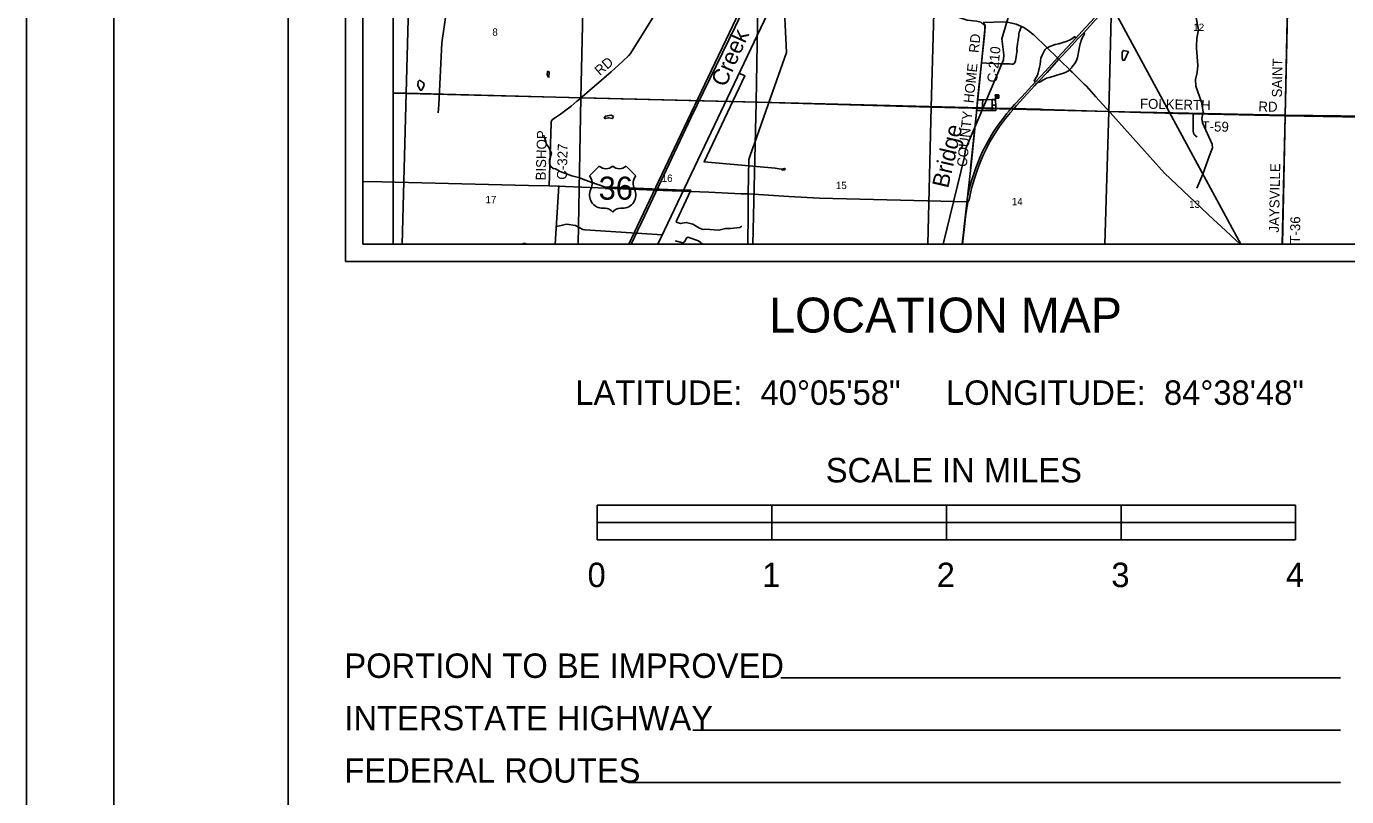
# Model space of a CAD drawing. Extents: x 0 to 68.9, y -26.1 to 22.
# Drawn here: x 0 to 7.56, y 10.94 to 15.35 of the extents above; entities that cross this region are included whole.
import ezdxf

# ---------------------------------------------------------------- set-up
doc = ezdxf.new("R2010")
doc.units = 0
for name, color, linetype in [('GM_X_Corporation', 7, 'Continuous'), ('GM_X_County_Road', 7, 'Continuous'), ('GM_X_County_Road_Text', 7, 'Continuous'), ('GM_X_Interchange_Ramps', 7, 'Continuous'), ('GM_X_Minor_Lake', 7, 'Continuous'), ('GM_X_Minor_River', 7, 'Continuous'), ('GM_X_Minor_River_Text', 7, 'Continuous'), ('GM_X_Rail_Line', 7, 'Continuous'), ('GM_X_Section_Text', 7, 'Continuous'), ('GM_X_State_Route', 7, 'Continuous'), ('GM_X_Township_Road', 7, 'Continuous'), ('GM_X_Township_Road_Text', 7, 'Continuous'), ('GM_X_US_Location', 7, 'Continuous'), ('GM_X_US_Route', 7, 'Continuous'), ('GM_X_US_Shield', 7, 'Continuous'), ('SH_Border', 7, 'Continuous'), ('SH_Cut_Line', 7, 'Continuous'), ('SH_Data', 7, 'Continuous'), ('SH_Text', 7, 'Continuous')]:
    doc.layers.add(name, color=color, linetype=linetype)

msp = doc.modelspace()

# ---------------------------------------------------------------- linework, layer by layer
at = {"layer": 'GM_X_Corporation'}
for points in [[(7.3445, 20.9), (2.1, 20.9), (2.1, 14.9646), (3.342, 14.9339), (4.4236, 14.9071), (5.6162, 14.8776), (5.6466, 14.8768), (5.7051, 14.8754), (5.7249, 14.8749), (5.8078, 14.8728), (5.8237, 14.8724), (6.3807, 14.8544), (6.5963, 14.8495), (6.6831, 14.8475), (7.2088, 14.8355), (7.7563, 14.8264), (8.2579, 14.8244), (8.6486, 14.8265), (8.7556, 14.8254), (8.9, 14.8227), (8.9, 20.8594), (8.5115, 20.8629), (7.8412, 20.8763), (7.3443, 20.8819)], [(2.1, 15.9546), (2.1, 14.9678), (2.1744, 14.9657), (2.2018, 15.9573)], [(2.2018, 15.9573), (3.1993, 15.9361), (3.1762, 14.938), (2.1744, 14.9657)], [(3.1993, 15.9361), (4.1977, 15.9225), (4.1789, 14.914), (3.1762, 14.938)], [(4.1977, 15.9225), (5.2101, 15.8972), (5.1829, 14.8851), (4.1789, 14.914)], [(5.2101, 15.8972), (6.224, 15.8733), (6.2001, 14.86), (5.1829, 14.8851)], [(6.224, 15.8733), (7.2305, 15.8522), (7.2304, 15.8453), (7.2092, 14.8389), (6.2001, 14.86)], [(8.019, 15.8387), (8.0065, 14.829), (7.2092, 14.8389), (7.2304, 15.8453)], [(2.1, 14.9678), (2.1, 14.1), (2.1524, 14.1), (2.1744, 14.9657)], [(2.1, 14.9646), (2.1, 14.1), (7.1934, 14.1), (7.2088, 14.8355), (6.6831, 14.8475), (6.5963, 14.8495), (6.3807, 14.8544), (5.8237, 14.8724), (5.8078, 14.8728), (5.7249, 14.8749), (5.7051, 14.8754), (5.6466, 14.8768), (5.6162, 14.8776), (4.4236, 14.9071), (3.342, 14.9339)], [(2.1524, 14.1), (3.1596, 14.1), (3.1762, 14.938), (2.1744, 14.9657)], [(3.1596, 14.1), (4.16, 14.1), (4.1789, 14.914), (3.1762, 14.938)], [(4.16, 14.1), (5.1627, 14.1), (5.1829, 14.8851), (4.1789, 14.914)], [(5.1627, 14.1), (6.1766, 14.1), (6.2001, 14.86), (5.1829, 14.8851)], [(6.1766, 14.1), (7.1943, 14.1), (7.2092, 14.8389), (6.2001, 14.86)], [(7.1934, 14.1), (8.9, 14.1), (8.9, 14.8227), (8.7556, 14.8254), (8.6486, 14.8265), (8.2579, 14.8244), (7.7563, 14.8264), (7.2088, 14.8355)], [(7.1943, 14.1), (8.0027, 14.1), (8.0065, 14.829), (7.2092, 14.8389)]]:
    msp.add_lwpolyline(points, close=True, dxfattribs=at)
at = {"layer": 'GM_X_County_Road'}
for p, q in [((5.532, 14.8967), (5.5316, 14.928)), ((5.532, 14.8967), (5.552, 14.8973)), ((5.5419, 14.928), (5.5512, 14.9199)), ((5.5498, 14.9454), (5.5693, 14.9454)), ((5.4071, 14.5356), (5.4413, 14.8553)), ((5.4423, 14.865), (5.4731, 14.8655))]:
    msp.add_line(p, q, dxfattribs=at)
for points in [[(3.1578, 14.9235), (3.1692, 14.9333), (3.3487, 15.0882), (3.417, 15.1494), (3.4479, 15.1782), (3.4593, 15.1916), (3.5611, 15.3554), (3.5951, 15.4107), (3.6052, 15.4306), (3.6308, 15.5213), (3.7157, 15.8576), (3.7173, 15.8579), (3.8308, 15.8195), (3.8677, 15.807), (3.9004, 15.7954), (3.9289, 15.7828), (3.9544, 15.7713), (4.0004, 15.7479), (4.0281, 15.7353), (4.0515, 15.7285), (4.2089, 15.7174)], [(5.4413, 14.8553), (5.4423, 14.865), (5.4435, 14.877), (5.4484, 14.9277), (5.4712, 15.1394), (5.4871, 15.297), (5.4923, 15.3449), (5.4911, 15.3529), (5.4798, 15.3701)], [(5.4712, 15.1394), (5.499, 15.1369), (5.5375, 15.1351), (5.5782, 15.1336), (5.6076, 15.1332), (5.6314, 15.1326), (5.6435, 15.1315), (5.6505, 15.1318), (5.6544, 15.1332), (5.6579, 15.1351), (5.6602, 15.1376), (5.6614, 15.1403), (5.6627, 15.1439), (5.6643, 15.1498), (5.6683, 15.1748), (5.6708, 15.187), (5.6734, 15.1998), (5.6738, 15.2087), (5.6735, 15.2153), (5.6733, 15.2218), (5.674, 15.2302), (5.6762, 15.2469), (5.6804, 15.2711), (5.6835, 15.2946), (5.685, 15.3051), (5.6865, 15.3153), (5.689, 15.323), (5.6935, 15.3329), (5.6996, 15.3464)], [(2.9943, 14.434), (3.0051, 14.7942), (3.0061, 14.8022), (3.0113, 14.8115), (3.0242, 14.8218), (3.0587, 14.8452), (3.0979, 14.8733), (3.1197, 14.8906), (3.1533, 14.9195), (3.1578, 14.9235)], [(5.4484, 14.9277), (5.4774, 14.9272), (5.5316, 14.928), (5.539, 14.928)], [(5.4731, 14.8655), (5.5324, 14.8657), (5.5523, 14.8655), (5.5522, 14.8744), (5.552, 14.8973), (5.5512, 14.9199), (5.5509, 14.928)], [(5.4731, 14.8655), (5.4738, 14.8763), (5.4774, 14.9272)], [(5.5324, 14.8657), (5.5323, 14.8748), (5.532, 14.8967)], [(5.539, 14.928), (5.5419, 14.928), (5.5509, 14.928), (5.5504, 14.9361), (5.5498, 14.9454), (5.5492, 14.9548), (5.5689, 14.9548), (5.5693, 14.9454), (5.5696, 14.9364), (5.5504, 14.9361)]]:
    msp.add_lwpolyline(points, dxfattribs=at)
at = {"layer": 'GM_X_Interchange_Ramps'}
for points in [[(6.012, 15.282), (6.0053, 15.2887), (6.0034, 15.2872), (5.9877, 15.2769), (5.9739, 15.2691), (5.9553, 15.2611), (5.9356, 15.2547), (5.9126, 15.2486), (5.8924, 15.2434), (5.8779, 15.2381), (5.8612, 15.2319), (5.8542, 15.2282), (5.8501, 15.2265), (5.8459, 15.2253)], [(5.9751, 15.0992), (5.9771, 15.1013), (5.985, 15.1109), (5.9877, 15.1139), (5.9962, 15.1239), (6.0045, 15.1346), (6.011, 15.1454), (6.0167, 15.1581), (6.0202, 15.1692), (6.0228, 15.1788), (6.032, 15.2308), (6.0337, 15.2386), (6.0362, 15.2499), (6.0384, 15.2579), (6.0417, 15.2672), (6.0498, 15.2858), (6.0544, 15.2945), (6.0585, 15.3008), (6.0611, 15.3048), (6.0556, 15.3101)], [(5.8459, 15.2253), (5.8428, 15.223), (5.8352, 15.2146), (5.8311, 15.2094), (5.8227, 15.1938), (5.8155, 15.1785), (5.8111, 15.1647), (5.8082, 15.1495), (5.8055, 15.1291), (5.8026, 15.1132), (5.7995, 15.0968), (5.795, 15.0814), (5.7903, 15.0685), (5.7838, 15.0549), (5.7757, 15.0411), (5.772, 15.036), (5.7792, 15.0294)], [(5.7969, 15.0328), (5.8035, 15.027), (5.8065, 15.0293), (5.8254, 15.0413), (5.843, 15.0502), (5.8578, 15.0557), (5.8785, 15.0614), (5.9022, 15.0675), (5.9215, 15.0734), (5.94, 15.0789), (5.9552, 15.0861), (5.9613, 15.0896), (5.9681, 15.0933), (5.9728, 15.0964), (5.9751, 15.0992)]]:
    msp.add_lwpolyline(points, dxfattribs=at)
at = {"layer": 'GM_X_Minor_Lake'}
for points in [[(6.3127, 15.2042), (6.2843, 15.2101), (6.2764, 15.1992), (6.2761, 15.1645)], [(6.2761, 15.1645), (6.2812, 15.1519), (6.2897, 15.1548), (6.3127, 15.2042)], [(2.995, 15.088), (2.9855, 15.0904), (2.9823, 15.0726), (2.99, 15.0557)], [(2.99, 15.0557), (2.9931, 15.0591), (2.995, 15.088)], [(2.2442, 15.0326), (2.2425, 15.0117), (2.2561, 14.9829), (2.2656, 14.9824)], [(2.2656, 14.9824), (2.2774, 15.0104), (2.2749, 15.0249), (2.2519, 15.0389), (2.2442, 15.0326)], [(3.3622, 14.8309), (3.3494, 14.8395), (3.3159, 14.8342), (3.3093, 14.8225)], [(3.3093, 14.8225), (3.3157, 14.8197), (3.3329, 14.8241), (3.356, 14.8196), (3.3622, 14.8309)], [(4.3486, 14.5306), (4.3399, 14.5333), (4.3232, 14.5301)], [(4.3232, 14.5301), (4.3292, 14.524), (4.3432, 14.5257), (4.3486, 14.5306)]]:
    msp.add_lwpolyline(points, dxfattribs=at)
at = {"layer": 'GM_X_Minor_River'}
for points in [[(5.2032, 17.5828), (5.134, 17.5588), (5.1121, 17.5421), (5.0972, 17.515), (5.0939, 17.5032), (5.0972, 17.4701), (5.0978, 17.4169), (5.0859, 17.3916), (5.0609, 17.373), (4.8668, 17.2013), (4.5171, 16.6592), (4.4995, 16.6291), (4.4797, 16.5807), (4.4638, 16.5175), (4.4595, 16.3547), (4.4585, 16.3449), (4.4481, 16.2914), (4.3439, 16.0443), (4.302, 15.5413), (3.617, 14.1)], [(5.866, 16.2613), (5.8254, 16.2239), (5.8128, 16.2158), (5.7904, 16.1522), (5.7129, 16.044), (5.7106, 15.9576), (5.6916, 15.8883), (5.6827, 15.6158), (5.6669, 15.5849), (5.6521, 15.4785), (5.6339, 15.4372), (5.5869, 15.2768), (5.5975, 15.1844), (5.5966, 15.1566), (5.379, 14.6444), (5.3722, 14.6003), (5.2503, 14.1)], [(6.7256, 15.5095), (6.698, 15.4431), (6.6982, 15.4069), (6.7125, 15.327), (6.7031, 15.2797), (6.7015, 15.2335), (6.7019, 15.2236), (6.7086, 15.1238), (6.7064, 15.0838), (6.6965, 15.0437), (6.6971, 15.0055), (6.7303, 14.9142), (6.7398, 14.8585), (6.7315, 14.8191), (6.7371, 14.7949), (6.7925, 14.6739), (6.794, 14.6513), (6.7756, 14.6077), (6.7386, 14.501), (6.7034, 14.4213)], [(2.4127, 15.4774), (2.3799, 15.2544), (2.3622, 14.8977), (2.3587, 14.8521)], [(4.083, 15.0804), (4.1145, 15.0648), (3.8811, 14.5715), (4.2886, 14.5348), (4.3232, 14.5301)], [(3.7644, 14.4102), (3.3115, 14.4277), (3.1956, 14.4682), (3.1696, 14.4808), (3.1238, 14.4912), (3.0573, 14.5163), (3.031, 14.5308), (3.0162, 14.5334), (3.0046, 14.545), (2.9965, 14.5596), (2.9954, 14.5825), (3.0067, 14.6189), (2.994, 14.6514), (2.9769, 14.675), (2.9753, 14.691), (2.9647, 14.7156), (2.9645, 14.7251)], [(3.7647, 14.4108), (3.8049, 14.4086), (3.7247, 14.2378), (3.7218, 14.2264), (3.7472, 14.2192), (3.7795, 14.2243), (3.8162, 14.2142), (3.8561, 14.1918), (3.8765, 14.1842), (3.8883, 14.1855), (3.9665, 14.1796), (4.0039, 14.1904), (4.032, 14.1895), (4.0865, 14.1962), (4.0984, 14.2028)], [(3.6427, 14.1541), (3.1989, 14.1826), (3.1879, 14.1839), (3.145, 14.2078), (3.0938, 14.2144), (3.0713, 14.2084), (3.037, 14.2021)], [(2.8373, 14.1), (2.8476, 14.1047), (2.859, 14.1036), (2.8602, 14.1)], [(3.7161, 14.1188), (3.7599, 14.1085), (3.7696, 14.1136), (3.7804, 14.1354), (3.7885, 14.1394), (3.7941, 14.1389), (3.8487, 14.1196), (3.8715, 14.1)]]:
    msp.add_lwpolyline(points, dxfattribs=at)
at = {"layer": 'GM_X_Rail_Line'}
for points in [[(5.3603, 14.1), (5.4108, 14.554), (5.4493, 14.931), (5.4886, 15.3274), (5.4889, 15.3505), (5.4662, 15.3724), (5.4429, 15.3781), (5.388, 15.3842), (5.3426, 15.3979), (5.3038, 15.4193), (5.2961, 15.4246), (5.2885, 15.4402), (5.2608, 15.718), (5.1953, 16.319), (5.1234, 16.9884), (5.1371, 16.996), (5.443, 16.9855), (5.445, 17.1132)], [(6.9557, 14.1), (6.658, 14.6501), (6.2728, 15.3624), (5.8705, 16.1031), (5.7903, 16.2402), (5.6933, 16.4263), (5.661, 16.5169), (5.6263, 16.6127), (5.6035, 16.684), (5.587, 16.7753), (5.5776, 16.8861), (5.579, 16.9902), (5.581, 17.0911)], [(3.4501, 14.1), (3.4974, 14.2017), (3.7112, 14.6522), (3.9429, 15.1376), (4.0085, 15.2728), (4.1571, 15.5871), (4.2174, 15.7254)], [(3.4647, 14.1), (3.5422, 14.2642), (3.8062, 14.8242), (4.0587, 15.346), (4.1507, 15.5403), (4.1687, 15.5853), (4.2174, 15.7254)]]:
    msp.add_lwpolyline(points, dxfattribs=at)
at = {"layer": 'GM_X_State_Route'}
for p, q in [((6.0591, 15.0164), (5.9891, 15.0854)), ((6.2057, 14.8564), (6.1261, 14.9441)), ((4.1336, 14.2758), (4.1342, 14.3876))]:
    msp.add_line(p, q, dxfattribs=at)
for points in [[(4.168, 14.6719), (4.2509, 14.9066), (4.3541, 15.1989), (4.3416, 15.4354), (4.3831, 15.7051)], [(5.7659, 15.302), (5.7456, 15.3179), (5.7127, 15.3407), (5.6697, 15.3595), (5.6267, 15.3696), (5.5885, 15.3736), (5.5417, 15.3723), (5.4798, 15.3701)], [(5.9103, 15.1621), (5.9057, 15.1666), (5.8459, 15.2253), (5.7675, 15.3008), (5.7659, 15.302)], [(5.9249, 15.1479), (5.9134, 15.1591), (5.9103, 15.1621)], [(5.9891, 15.0854), (5.9751, 15.0992), (5.9723, 15.102), (5.9249, 15.1479)], [(6.1261, 14.9441), (6.071, 15.0047), (6.0591, 15.0164)], [(6.8202, 14.2216), (6.8018, 14.2386), (6.5179, 14.5073), (6.208, 14.8539), (6.2057, 14.8564)], [(4.1342, 14.3876), (4.1375, 14.5855), (4.1653, 14.6643), (4.168, 14.6719)], [(4.1328, 14.1), (4.1336, 14.2737), (4.1336, 14.2758)], [(6.9521, 14.1), (6.8431, 14.2004), (6.8202, 14.2216)]]:
    msp.add_lwpolyline(points, dxfattribs=at)
at = {"layer": 'GM_X_Township_Road'}
for p, q in [((7.209, 14.835), (7.232, 15.8435)), ((6.3787, 14.8564), (6.5946, 14.849)), ((7.1936, 14.1), (7.209, 14.835))]:
    msp.add_line(p, q, dxfattribs=at)
for points in [[(6.5946, 14.849), (6.5966, 14.8489), (6.6833, 14.847), (7.209, 14.835)], [(6.7054, 14.7144), (6.7007, 14.717), (6.6991, 14.7181), (6.6962, 14.7203), (6.6938, 14.7227), (6.6915, 14.7253), (6.6886, 14.7295), (6.6874, 14.7316), (6.6866, 14.7334), (6.6853, 14.7366), (6.6846, 14.739), (6.6838, 14.7422), (6.6835, 14.7443), (6.6834, 14.7459), (6.6832, 14.749), (6.6833, 14.7516), (6.6833, 14.847)], [(7.209, 14.835), (7.7566, 14.8259), (8.2582, 14.8239)], [(3.0276, 14.1), (3.0472, 14.4014), (3.0486, 14.4367)]]:
    msp.add_lwpolyline(points, dxfattribs=at)
at = {"layer": 'GM_X_US_Route'}
for p, q in [((5.7903, 15.0248), (5.7969, 15.0328)), ((5.3624, 14.1), (5.3752, 14.2176))]:
    msp.add_line(p, q, dxfattribs=at)
for points in [[(6.0556, 15.3101), (6.1394, 15.4015), (6.2009, 15.4689), (6.2873, 15.562), (6.3509, 15.6318), (6.3799, 15.666), (6.4089, 15.7035), (6.4302, 15.7332), (6.4519, 15.7645), (6.4678, 15.7909), (6.491, 15.8329), (6.5094, 15.8686)], [(5.7792, 15.0294), (5.8363, 15.0914), (5.9057, 15.1666), (5.9619, 15.2273), (6.012, 15.282), (6.0454, 15.3181), (6.1185, 15.3975)], [(5.912, 15.1576), (5.9134, 15.1591), (5.972, 15.2208), (6.0209, 15.2745), (6.0556, 15.3101)], [(5.7969, 15.0328), (5.8458, 15.0843), (5.912, 15.1576)], [(5.3914, 14.3426), (5.3885, 14.3567), (5.3907, 14.3691), (5.3956, 14.3933), (5.4007, 14.4152), (5.4101, 14.4522), (5.4186, 14.4808), (5.4278, 14.5093), (5.4373, 14.5366), (5.4489, 14.5662), (5.4631, 14.6002), (5.477, 14.6302), (5.4962, 14.6687), (5.5105, 14.6943), (5.5359, 14.7375), (5.55, 14.7599), (5.5673, 14.7857), (5.5993, 14.8285), (5.613, 14.8458), (5.6281, 14.8645), (5.635, 14.8723), (5.6594, 14.8995), (5.7009, 14.9449), (5.7586, 15.0071), (5.7792, 15.0294)], [(5.3914, 14.3426), (5.3992, 14.3549), (5.4054, 14.3831), (5.4153, 14.4259), (5.4297, 14.4761), (5.4466, 14.5281), (5.4589, 14.5593), (5.4705, 14.5869), (5.4822, 14.6135), (5.4988, 14.6479), (5.519, 14.6864), (5.5444, 14.7296), (5.5743, 14.7744), (5.6078, 14.8207), (5.6361, 14.8549), (5.651, 14.8719), (5.6702, 14.8938), (5.7113, 14.9385), (5.7745, 15.0064), (5.7877, 15.0216), (5.7903, 15.0248)], [(1.927, 14.46), (2.0353, 14.4566), (2.8756, 14.4367), (2.9943, 14.434), (3.3688, 14.4187), (3.6467, 14.4079), (3.9078, 14.3971), (4.0945, 14.3892), (4.1342, 14.3876)], [(4.1342, 14.3876), (4.3672, 14.3736), (4.5422, 14.3644), (5.3914, 14.3426)], [(5.3752, 14.2176), (5.3797, 14.2595), (5.3914, 14.3426)]]:
    msp.add_lwpolyline(points, dxfattribs=at)
at = {"layer": 'GM_X_US_Shield'}
for p, q in [((3.281, 14.5474), (3.2261, 14.4925)), ((3.4898, 14.4925), (3.4348, 14.5474)), ((3.303, 14.3057), (3.314, 14.3057)), ((3.4019, 14.3057), (3.4129, 14.3057))]:
    msp.add_line(p, q, dxfattribs=at)
for centre, radius, start, end in [((3.3195, 14.5866), 0.0549, 225.573, 314.427), ((3.3964, 14.5866), 0.0549, 225.573, 314.427), ((3.1631, 14.4483), 0.0769, 334.54712, 35.00093), ((3.5528, 14.4483), 0.0769, 144.99907, 205.45288), ((3.3021, 14.3826), 0.0769, 154.83192, 270.63826), ((3.4137, 14.3826), 0.0769, 269.36174, 25.16808), ((3.314, 14.2508), 0.0549, 36.8699, 90), ((3.4019, 14.2508), 0.0549, 90, 143.1301)]:
    msp.add_arc(centre, radius, start, end, dxfattribs=at)
at = {"layer": 'SH_Border'}
for points in [[(0.5, 21.5), (1.5, 21.5), (1.5, 0.5), (0.5, 0.5)], [(1.5, 21.5), (33.5, 21.5), (33.5, 0.5), (1.5, 0.5)]]:
    msp.add_lwpolyline(points, close=True, dxfattribs=at)
at = {"layer": 'SH_Cut_Line'}
msp.add_lwpolyline([(0, 0), (34, 0), (34, 22), (0, 22)], close=True, dxfattribs=at)
at = {"layer": 'SH_Data'}
for p, q in [((1.827, 21), (1.827, 14)), ((1.927, 20.9), (1.927, 14.1)), ((1.927, 14.1), (8.727, 14.1)), ((1.927, 14.1), (1.927, 14.1)), ((1.827, 14), (8.827, 14)), ((7.527, 11.6154), (4.3207, 11.6154)), ((7.527, 11.3154), (3.8165, 11.3154)), ((7.527, 11.0154), (3.4462, 11.0154))]:
    msp.add_line(p, q, dxfattribs=at)
at = {"layer": 'SH_Text'}
for p, q in [((3.2696, 12.6055), (5.2696, 12.6055)), ((3.2696, 12.6055), (3.2696, 12.4055)), ((4.2696, 12.6055), (4.2696, 12.4055)), ((5.2696, 12.6055), (7.2696, 12.6055)), ((5.2696, 12.6055), (5.2696, 12.4055)), ((6.2696, 12.6055), (6.2696, 12.4055)), ((7.2696, 12.6055), (7.2696, 12.4055)), ((3.2696, 12.5055), (5.2696, 12.5055)), ((5.2696, 12.5055), (7.2696, 12.5055)), ((3.2696, 12.4055), (5.2696, 12.4055)), ((5.2696, 12.4055), (7.2696, 12.4055))]:
    msp.add_line(p, q, dxfattribs=at)
for points in [[(3.2696, 12.6055), (4.2696, 12.6055), (4.2696, 12.5055), (3.2696, 12.5055)], [(5.2696, 12.6055), (6.2696, 12.6055), (6.2696, 12.5055), (5.2696, 12.5055)], [(5.2696, 12.4055), (4.2696, 12.4055), (4.2696, 12.5055), (5.2696, 12.5055)], [(7.2696, 12.4055), (6.2696, 12.4055), (6.2696, 12.5055), (7.2696, 12.5055)]]:
    msp.add_lwpolyline(points, close=True, dxfattribs=at)

# ---------------------------------------------------------------- texts
at = {"layer": 'GM_X_County_Road_Text'}
for s, rotation, p in [('RD', 84.09386, (5.454, 15.1937)), ('C-210', 84.20724, (5.5586, 15.0239)), ('RD', 41.27594, (3.2851, 15.0625)), ('HOME', 83.93229, (5.424, 14.9061)), ('COUNTY', 84.04284, (5.3857, 14.5403)), ('BISHOP', 88.45175, (2.9739, 14.4645)), ('C-327', 88.34781, (3.0949, 14.4685))]:
    msp.add_text(s, height=0.05682, rotation=rotation, dxfattribs=at).set_placement(p)
at = {"layer": 'GM_X_Minor_River_Text'}
for s, height, rotation, p in [('Creek', 0.09486, 66.00509, (4.0039, 14.9952)), ('Bridge', 0.0949, 76.97874, (5.2789, 14.4165))]:
    msp.add_text(s, height=height, rotation=rotation, dxfattribs=at).set_placement(p)
at = {"layer": 'GM_X_Section_Text'}
for s, height, p in [('12', 0.04186, (6.6834, 15.3217)), ('8', 0.0419, (2.6688, 15.2939)), ('16', 0.04186, (3.6388, 14.4572)), ('15', 0.04186, (4.6363, 14.4157)), ('17', 0.04186, (2.6297, 14.3344)), ('14', 0.04186, (5.6442, 14.3234)), ('13', 0.04186, (6.6597, 14.3081))]:
    msp.add_text(s, height=height, rotation=0.00001, dxfattribs=at).set_placement(p)
at = {"layer": 'GM_X_Township_Road_Text'}
for s, rotation, p in [('SAINT', 88.83082, (7.1902, 14.9401)), ('FOLKERTH', 358.6861, (6.3774, 14.877)), ('RD', 358.51936, (7.0557, 14.8612)), ('T-59', 358.585, (6.7301, 14.7478)), ('JAYSVILLE', 88.82822, (7.1736, 14.166)), ('T-36', 88.74196, (7.2934, 14.1026))]:
    msp.add_text(s, height=0.05682, rotation=rotation, dxfattribs=at).set_placement(p)
at = {"layer": 'GM_X_US_Location'}
msp.add_text('36', height=0.000189, rotation=0.00001, dxfattribs=at).set_placement((3.3188, 14.3808))
for s in ['0', '/']:
    msp.add_text(s, height=0.000189, dxfattribs=at).set_placement((3.3579, 14.42))
at = {"layer": 'GM_X_US_Shield'}
msp.add_text('36', height=0.13184, dxfattribs=at).set_placement((3.2775, 14.3551))
at = {"layer": 'SH_Text'}
for s, height, p in [('LOCATION MAP', 0.2, (4.2539, 13.5938)), ('LATITUDE:  40°05\'58"     LONGITUDE:  84°38\'48"', 0.14, (3.1441, 13.1796)), ('SCALE IN MILES', 0.14, (4.5786, 12.7355)), ('0', 0.14, (3.214, 12.1355)), ('1', 0.14, (4.214, 12.1355)), ('2', 0.14, (5.214, 12.1355)), ('3', 0.14, (6.214, 12.1355)), ('4', 0.14, (7.214, 12.1355)), ('PORTION TO BE IMPROVED', 0.14, (1.8214, 11.6154)), ('INTERSTATE HIGHWAY', 0.14, (1.8214, 11.3154)), ('FEDERAL ROUTES', 0.14, (1.8214, 11.0154))]:
    msp.add_text(s, height=height, dxfattribs=at).set_placement(p)

doc.saveas('drawing.dxf')
